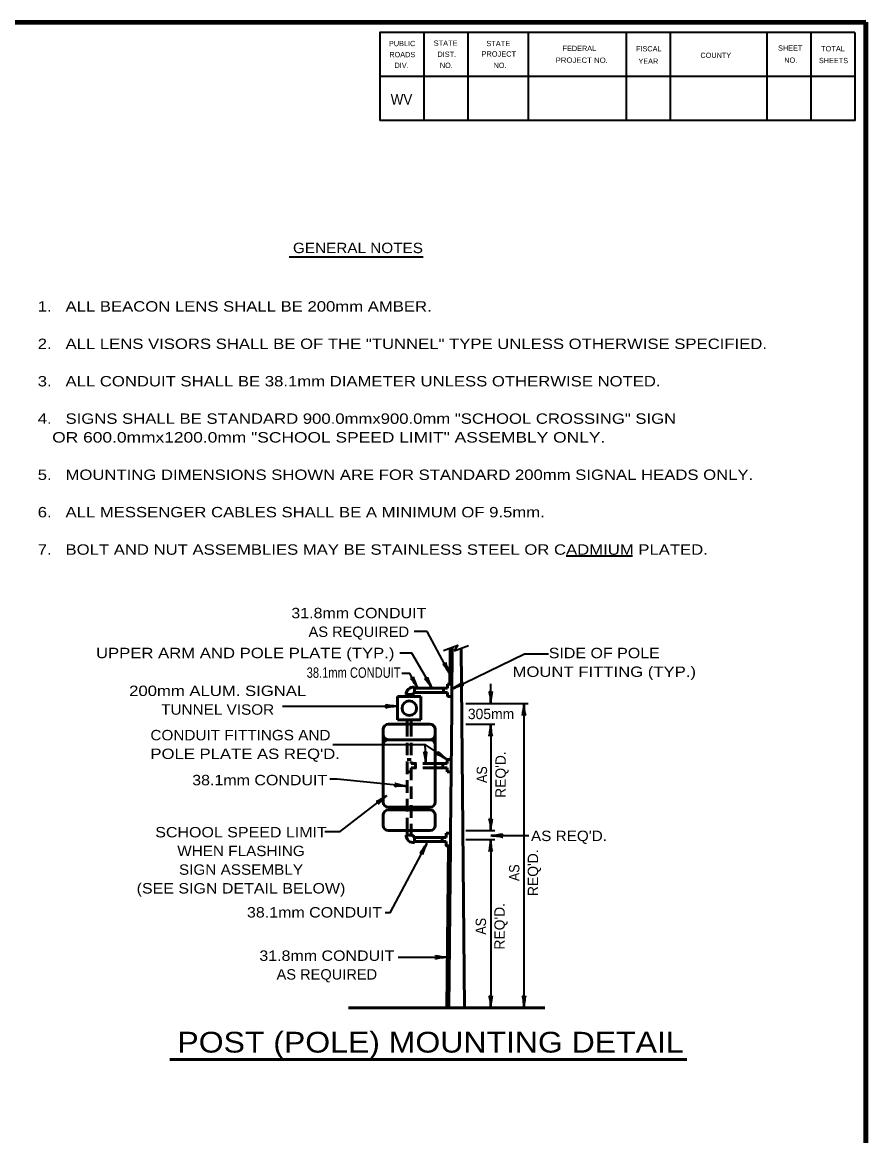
# Model space of a CAD drawing. Extents: x -35 to 821, y -10 to 534.
# Drawn here: x 571 to 814.4, y 205.9 to 527.4 of the extents above; entities that cross this region are included whole.
import ezdxf
from ezdxf.enums import TextEntityAlignment as Align

# ---------------------------------------------------------------- set-up
doc = ezdxf.new("R2010")
doc.units = 0
doc.header["$LTSCALE"] = 1.2
doc.linetypes.add('MEDIUM_DASHED', pattern=[4.5, 3, -1.5])
doc.layers.add('1', color=7, linetype='Continuous', lineweight=35)
doc.layers.add('61', color=7, linetype='Continuous', lineweight=35)

msp = doc.modelspace()

# ---------------------------------------------------------------- linework, layer by layer
at = {"layer": '1', "lineweight": 158}
msp.add_line((814.384, 1.25), (814.384, 527.35), dxfattribs=at)
at = {"layer": '1', "lineweight": 13}
msp.add_line((814.384, 1.25), (814.384, 527.35), dxfattribs=at)
at = {"layer": '1'}
for p, q in [((648.01, 459.666), (686.689, 459.666)), ((727.899, 373.263), (747.058, 373.263)), ((687.848, 351.485), (684.016, 351.485)), ((694.364, 339.199), (687.848, 351.485)), ((692.507, 345.946), (696.701, 347.491)), ((696.701, 347.491), (695.597, 345.835)), ((695.597, 345.835), (699.79, 347.381)), ((695.122, 334.954), (715.867, 345.043)), ((715.867, 345.043), (722.849, 345.043)), ((706.149, 330.685), (706.149, 336.347)), ((646.098, 329.883), (679.251, 329.883)), ((698.949, 330.685), (716.949, 330.685)), ((715.749, 330.685), (715.749, 242.825)), ((698.949, 324.712), (707.349, 324.712)), ((706.149, 324.712), (706.149, 293.962)), ((687.149, 318.866), (687.399, 313.312)), ((698.949, 293.962), (707.349, 293.962)), ((706.154, 292.544), (717.192, 292.544)), ((698.949, 291.389), (707.349, 291.389)), ((706.149, 291.389), (706.149, 242.825)), ((679.408, 257.407), (693.63, 257.407))]:
    msp.add_line(p, q, dxfattribs=at)
at = {"layer": '1', "lineweight": 53}
for p, q in [((694.457, 346.664), (694.36, 336.262)), ((695.059, 346.886), (694.926, 332.512)), ((697.601, 346.574), (698.562, 242.811)), ((684.124, 335.362), (684.124, 333.562)), ((693.726, 335.062), (684.124, 335.062)), ((692.526, 335.062), (692.526, 333.862)), ((694.926, 336.262), (693.726, 336.262)), ((693.726, 336.262), (693.726, 335.062)), ((679.251, 332.662), (686.001, 332.662)), ((679.251, 332.662), (679.251, 325.912)), ((681.726, 333.262), (683.526, 333.262)), ((682.026, 332.662), (682.026, 333.262)), ((683.226, 332.662), (683.226, 333.262)), ((693.726, 333.862), (684.124, 333.862)), ((686.001, 332.662), (686.001, 325.912)), ((693.726, 332.662), (693.726, 333.862)), ((694.892, 332.662), (693.726, 332.662)), ((676.626, 324.712), (688.626, 324.712)), ((679.251, 325.912), (686.001, 325.912)), ((682.026, 325.912), (682.026, 324.712)), ((683.226, 325.912), (683.226, 324.712)), ((675.126, 323.212), (675.126, 302.212)), ((690.126, 323.212), (690.126, 302.212)), ((676.626, 320.212), (688.626, 320.212)), ((683.226, 314.512), (682.026, 314.512)), ((684.426, 313.312), (684.426, 312.112)), ((693.559, 313.312), (690.126, 313.312)), ((693.559, 312.112), (690.126, 312.112)), ((692.359, 313.312), (692.359, 312.112)), ((694.759, 314.512), (693.559, 314.512)), ((693.559, 314.512), (693.559, 313.312)), ((693.559, 310.912), (693.559, 312.112)), ((683.226, 310.912), (682.026, 310.912)), ((694.759, 310.912), (693.559, 310.912)), ((676.626, 300.712), (688.626, 300.712)), ((676.626, 299.962), (688.626, 299.962)), ((675.126, 298.462), (675.126, 295.462)), ((690.126, 298.462), (690.126, 295.462)), ((676.626, 293.962), (688.626, 293.962)), ((681.726, 292.623), (683.526, 292.623)), ((682.026, 293.962), (682.026, 292.623)), ((683.226, 293.962), (683.226, 292.623)), ((693.333, 293.223), (693.333, 292.023)), ((694.562, 293.223), (693.333, 293.223)), ((694.562, 293.223), (694.136, 293.223)), ((684.124, 290.523), (684.124, 292.322)), ((693.333, 292.023), (684.124, 292.023)), ((693.333, 290.822), (684.124, 290.822)), ((692.133, 290.822), (692.133, 292.023)), ((693.929, 289.628), (693.495, 242.817)), ((665.129, 242.825), (721.749, 242.825)), ((613.502, 227.894), (762.738, 227.894))]:
    msp.add_line(p, q, dxfattribs=at)
at = {"layer": '1', "linetype": 'MEDIUM_DASHED', "lineweight": 53}
for p, q in [((682.026, 324.712), (682.026, 293.962)), ((683.226, 324.712), (683.226, 313.312)), ((690.126, 313.312), (683.226, 313.312)), ((690.126, 312.112), (683.226, 312.112)), ((683.226, 312.112), (683.226, 293.962))]:
    msp.add_line(p, q, dxfattribs=at)
at = {"layer": '1', "lineweight": 158}
msp.add_lwpolyline([(814.384, 527.35), (22.684, 527.25), (22.784, 1.25)], dxfattribs=at)
at = {"layer": '1'}
for points in [[(679.891, 345.266), (683.321, 345.266), (689.235, 335.062)], [(685.063, 335.062), (682.815, 339.301), (680.473, 339.301)], [(660.603, 318.866), (687.149, 318.866), (693.559, 314.512)], [(681.861, 306.821), (661.88, 308.803), (659.699, 308.803)], [(658.259, 293.733), (662.658, 293.733), (676.166, 304.13)], [(687.735, 290.339), (677.058, 270.209), (675.679, 270.209)]]:
    msp.add_lwpolyline(points, dxfattribs=at)
at = {"layer": '1', "lineweight": 53}
for points in [[(694.926, 332.512), (694.892, 328.912), (694.562, 293.223), (694.529, 289.623), (694.095, 242.811)], [(694.529, 289.623), (693.333, 289.623), (693.333, 290.822)]]:
    msp.add_lwpolyline(points, dxfattribs=at)
msp.add_circle((682.665, 329.321), 2.109, dxfattribs=at)
for centre, radius, start, end in [((683.87, 333.232), 2.145, 83.20694, 179.20989), ((684.01, 333.042), 0.532, 77.63194, 155.64369), ((676.626, 323.212), 1.5, 90, 180), ((688.626, 323.212), 1.5, 0, 90), ((676.626, 321.712), 1.5, 180, 270), ((688.626, 321.712), 1.5, 270, 0), ((676.626, 318.712), 1.5, 90, 180), ((688.626, 318.712), 1.5, 0, 90), ((676.626, 302.212), 1.5, 180, 270), ((688.626, 302.212), 1.5, 270, 0), ((676.626, 298.462), 1.5, 90, 180), ((688.626, 298.462), 1.5, 0, 90), ((676.626, 295.462), 1.5, 180, 270), ((683.87, 292.652), 2.145, 180.79011, 276.79306), ((684.01, 292.842), 0.532, 204.35631, 282.36806), ((688.626, 295.462), 1.5, 270, 0)]:
    msp.add_arc(centre, radius, start, end, dxfattribs=at)
at = {"layer": '1', "lineweight": 40}
for centre, major_axis, ratio, start_param, end_param in [((693.461, 340.215), (1.17, -1.805), 0.122415, 0.8963533, 3.1415927), ((693.962, 340.52), (0.801, -1.961), 0.07063, 3.1407148, 5.41811), ((684.16, 336.077), (1.17, -1.805), 0.122415, 0.8963533, 3.1415927), ((684.661, 336.383), (0.801, -1.961), 0.07063, 3.1407148, 5.41811), ((688.291, 336.028), (1.237, -1.76), 0.122415, 0.8963533, 3.1415927), ((688.78, 336.352), (-0.875, 1.929), 0.07063, 6.2823074, 8.5597026), ((696.155, 335.825), (-1.845, -1.106), 0.122415, 0.8963533, 3.1415927), ((696.442, 335.314), (-1.988, -0.732), 0.07063, 3.1407148, 5.41811), ((705.817, 331.995), (0.187, -2.143), 0.122415, 0.8963533, 3.1415927), ((706.402, 332.03), (-0.211, -2.108), 0.07063, 3.1407148, 5.41811), ((677.941, 329.552), (2.143, 0.187), 0.122415, 0.8963533, 3.1415927), ((677.906, 330.137), (2.108, -0.211), 0.07063, 3.1407148, 5.41811), ((715.495, 329.341), (0.211, 2.108), 0.07063, 3.1407148, 5.41811), ((716.08, 329.376), (-0.187, 2.143), 0.122415, 0.8963533, 3.1415927), ((705.895, 323.367), (0.211, 2.108), 0.07063, 3.1407148, 5.41811), ((705.895, 323.367), (0.211, 2.108), 0.07063, 3.1407148, 5.41811), ((706.48, 323.402), (-0.187, 2.143), 0.122415, 0.8963533, 3.1415927), ((706.48, 323.402), (-0.187, 2.143), 0.122415, 0.8963533, 3.1415927), ((687.009, 314.605), (0.284, -2.132), 0.122415, 0.8963533, 3.1415927), ((687.009, 314.605), (0.284, -2.132), 0.122415, 0.8963533, 3.1415927), ((687.592, 314.666), (-0.115, -2.115), 0.07063, 3.1407148, 5.41811), ((687.592, 314.666), (-0.115, -2.115), 0.07063, 3.1407148, 5.41811), ((692.29, 314.973), (1.878, -1.049), 0.122415, 0.8963533, 3.1415927), ((692.589, 315.477), (1.625, -1.359), 0.07063, 3.1407148, 5.41811), ((680.525, 306.62), (2.151, -0.025), 0.122415, 0.8963533, 3.1415927), ((680.525, 306.62), (2.151, -0.025), 0.122415, 0.8963533, 3.1415927), ((680.548, 307.206), (2.077, -0.418), 0.07063, 3.1407148, 5.41811), ((680.548, 307.206), (2.077, -0.418), 0.07063, 3.1407148, 5.41811), ((674.924, 303.58), (1.812, 1.159), 0.122415, 3.1415927, 5.386832), ((675.253, 303.095), (1.542, 1.453), 0.07063, 0.8650754, 3.1424706), ((705.817, 295.271), (0.187, -2.143), 0.122415, 0.8963533, 3.1415927), ((705.817, 295.271), (0.187, -2.143), 0.122415, 0.8963533, 3.1415927), ((706.402, 295.306), (-0.211, -2.108), 0.07063, 3.1407148, 5.41811), ((706.402, 295.306), (-0.211, -2.108), 0.07063, 3.1407148, 5.41811), ((707.498, 292.29), (-2.108, 0.211), 0.07063, 3.1407148, 5.41811), ((707.498, 292.29), (-2.108, 0.211), 0.07063, 3.1407148, 5.41811), ((707.463, 292.875), (-2.143, -0.187), 0.122415, 0.8963533, 3.1415927), ((707.463, 292.875), (-2.143, -0.187), 0.122415, 0.8963533, 3.1415927), ((686.828, 289.338), (1.17, 1.805), 0.122415, 3.1415927, 5.386832), ((686.828, 289.338), (1.17, 1.805), 0.122415, 3.1415927, 5.386832), ((687.329, 289.033), (0.801, 1.961), 0.07063, 0.8650754, 3.1424706), ((687.329, 289.033), (0.801, 1.961), 0.07063, 0.8650754, 3.1424706), ((705.895, 290.045), (0.211, 2.108), 0.07063, 3.1407148, 5.41811), ((705.895, 290.045), (0.211, 2.108), 0.07063, 3.1407148, 5.41811), ((706.48, 290.08), (-0.187, 2.143), 0.122415, 0.8963533, 3.1415927), ((706.48, 290.08), (-0.187, 2.143), 0.122415, 0.8963533, 3.1415927), ((692.321, 257.076), (2.143, 0.187), 0.122415, 0.8963533, 3.1415927), ((692.321, 257.076), (2.143, 0.187), 0.122415, 0.8963533, 3.1415927), ((692.286, 257.661), (2.108, -0.211), 0.07063, 3.1407148, 5.41811), ((692.286, 257.661), (2.108, -0.211), 0.07063, 3.1407148, 5.41811), ((705.817, 244.134), (0.187, -2.143), 0.122415, 0.8963533, 3.1415927), ((705.817, 244.134), (0.187, -2.143), 0.122415, 0.8963533, 3.1415927), ((706.402, 244.17), (-0.211, -2.108), 0.07063, 3.1407148, 5.41811), ((706.402, 244.17), (-0.211, -2.108), 0.07063, 3.1407148, 5.41811), ((715.417, 244.134), (0.187, -2.143), 0.122415, 0.8963533, 3.1415927), ((715.417, 244.134), (0.187, -2.143), 0.122415, 0.8963533, 3.1415927), ((716.002, 244.17), (-0.211, -2.108), 0.07063, 3.1407148, 5.41811), ((716.002, 244.17), (-0.211, -2.108), 0.07063, 3.1407148, 5.41811)]:
    msp.add_ellipse(centre, major_axis=major_axis, ratio=ratio, start_param=start_param, end_param=end_param, dxfattribs=at)
at = {"layer": '61'}
for p, q in [((686.884, 524.35), (686.884, 498.95)), ((699.584, 524.35), (699.584, 498.95)), ((716.984, 524.35), (716.984, 498.95)), ((745.284, 524.35), (745.284, 498.95)), ((757.984, 524.35), (757.984, 498.95)), ((785.884, 524.35), (785.884, 498.95)), ((798.584, 524.35), (798.584, 498.95)), ((811.284, 511.65), (674.184, 511.65))]:
    msp.add_line(p, q, dxfattribs=at)
for points in [[(811.284, 524.35), (674.184, 524.35), (674.184, 498.95)], [(811.284, 524.35), (811.284, 498.95), (674.184, 498.95)]]:
    msp.add_lwpolyline(points, dxfattribs=at)

# ---------------------------------------------------------------- texts
at = {"layer": '1'}
for s, height, width, p in [('WV', 3.048, 0.95, (677.284, 503.55)), ('GENERAL NOTES', 3, 1.1, (649.078, 460.698)), ('1.   ALL BEACON LENS SHALL BE 200mm AMBER.', 3, 1.2, (575.415, 443.817)), ('2.   ALL LENS VISORS SHALL BE OF THE "TUNNEL" TYPE UNLESS OTHERWISE SPECIFIED.', 3, 1.2, (575.415, 433.017)), ('3.   ALL CONDUIT SHALL BE 38.1mm DIAMETER UNLESS OTHERWISE NOTED.', 3, 1.2, (575.415, 422.217)), ('4.   SIGNS SHALL BE STANDARD 900.0mmx900.0mm "SCHOOL CROSSING" SIGN', 3, 1.2, (575.415, 411.417)), ('   OR 600.0mmx1200.0mm "SCHOOL SPEED LIMIT" ASSEMBLY ONLY.', 3, 1.25, (575.415, 406.017)), ('5.   MOUNTING DIMENSIONS SHOWN ARE FOR STANDARD 200mm SIGNAL HEADS ONLY.', 3, 1.2, (575.415, 395.217)), ('6.   ALL MESSENGER CABLES SHALL BE A MINIMUM OF 9.5mm.', 3, 1.2, (575.415, 384.417)), ('7.   BOLT AND NUT ASSEMBLIES MAY BE STAINLESS STEEL OR CADMIUM PLATED.', 3, 1.2, (575.415, 373.617)), ('UPPER ARM AND POLE PLATE (TYP.)', 3, 1.2, (592.235, 343.756)), ('CONDUIT FITTINGS AND', 3, 1.1, (607.938, 320.046)), ("POLE PLATE AS REQ'D.", 3, 1.2, (607.938, 314.646)), ('38.1mm CONDUIT', 3, 1.15, (620.002, 307.067)), ('38.1mm CONDUIT', 3, 1.15, (635.804, 268.883)), ('POST (POLE) MOUNTING DETAIL', 6, 1.15, (615.722, 229.89))]:
    msp.add_text(s, height=height, dxfattribs=dict(at, width=width)).set_placement(p)
for s, width, p in [('31.8mm CONDUIT', 1.15, (668.093, 355.289)), ('AS REQUIRED', 1.05, (668.093, 349.889)), ('SIDE OF POLE', 1.15, (738.925, 343.75)), ('38.1mm CONDUIT', 0.8, (666.589, 338.088)), ('MOUNT FITTING (TYP.)', 1.2, (738.925, 338.35)), ('200mm ALUM. SIGNAL', 1.2, (627.354, 332.832)), ('TUNNEL VISOR', 1.1, (627.354, 327.432)), ('SCHOOL SPEED LIMIT', 1.15, (634.083, 292.018)), ("AS REQ'D.", 1.1, (728.741, 290.957)), ('WHEN FLASHING', 1.1, (634.082, 286.618)), ('SIGN ASSEMBLY', 1.1, (634.083, 281.218)), ('(SEE SIGN DETAIL BELOW)', 1.15, (634.082, 275.818)), ('31.8mm CONDUIT', 1.15, (658.861, 256.367)), ('AS REQUIRED', 1.05, (658.861, 250.967))]:
    msp.add_text(s, height=3, dxfattribs=dict(at, width=width)).set_placement(p, align=Align.CENTER)
msp.add_text('305mm', height=3, dxfattribs=at).set_placement((706.246, 326.16), align=Align.CENTER)
for p in [(710.496, 310.145), (719.838, 281.812), (710.203, 266.349)]:
    msp.add_text("REQ'D.", height=3, rotation=90, dxfattribs=at).set_placement(p, align=Align.CENTER)
at = {"layer": '1', "width": 0.9}
for p in [(705.096, 310.145), (714.438, 281.812), (704.803, 266.349)]:
    msp.add_text('AS', height=3, rotation=90, dxfattribs=at).set_placement(p, align=Align.CENTER)
at = {"layer": '61'}
for s, height, rotation, p in [('PUBLIC', 1.525, 0.033, (676.784, 520.45)), ('ROADS', 1.525, 0.124, (676.884, 517.25)), ('DIST.', 1.525, 0.056, (690.784, 517.35)), ('FEDERAL', 1.523, 0.007, (726.884, 519.05)), ('FISCAL', 1.525, 359.942, (748.084, 518.95)), ('COUNTY', 1.523, 0.069, (766.684, 517.05)), ('SHEET', 1.525, 0.059, (789.084, 519.15)), ('DIV.', 1.525, 359.932, (678.384, 514.15)), ('YEAR', 1.523, 0.105, (748.784, 515.35)), ('SHEETS', 1.523, 359.959, (800.884, 515.55))]:
    msp.add_text(s, height=height, rotation=rotation, dxfattribs=at).set_placement(p)
for s, rotation, width, p in [('STATE', 0.059, 1.05, (689.684, 520.55)), ('STATE', 0.059, 1.05, (704.884, 520.45)), ('PROJECT', 359.908, 1.05, (703.484, 517.45)), ('TOTAL', 359.926, 1.05, (801.484, 518.95)), ('NO.', 359.852, 0.9, (691.484, 514.15)), ('NO.', 0.225, 0.9, (706.984, 514.15)), ('PROJECT NO.', 359.922, 1.1, (724.884, 515.65)), ('NO.', 359.852, 0.9, (790.884, 515.65))]:
    msp.add_text(s, height=1.525, rotation=rotation, dxfattribs=dict(at, width=width)).set_placement(p)

doc.saveas('drawing.dxf')
